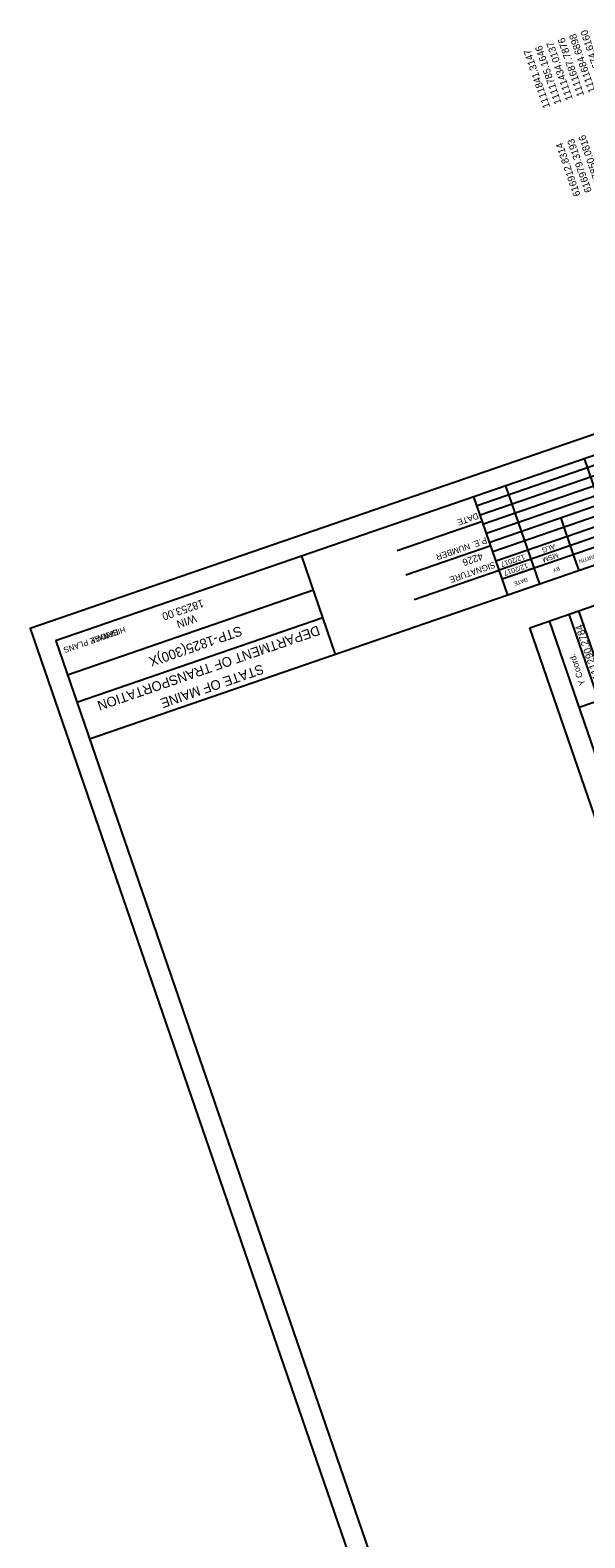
# Model space of a CAD drawing. Extents: x 1111039 to 1111836, y 617707 to 618808.
# Drawn here: x 1111039 to 1111305, y 618074 to 618798 of the extents above; entities that cross this region are included whole.
import ezdxf

# ---------------------------------------------------------------- set-up
doc = ezdxf.new("R2010")
doc.units = 0
for name, color, linetype in [('ANNOTATION', 7, 'Continuous'), ('BORDER', 7, 'Continuous'), ('BRIDGE_TITLE', 7, 'Continuous'), ('H_V CONTROLS', 7, 'Continuous'), ('HIGHWAY_TITLE', 7, 'Continuous'), ('PLOT BOUNDARY', 7, 'Continuous')]:
    doc.layers.add(name, color=color, linetype=linetype)

msp = doc.modelspace()

# ---------------------------------------------------------------- linework, layer by layer
at = {"layer": 'BORDER'}
for p, q in [((1111547.51, 618675.96), (1111051.11, 618505.04)), ((1111563.79, 618628.69), (1111067.39, 618457.77)), ((1111268.31, 618526.95), (1111252.03, 618574.22)), ((1111256.1, 618562.41), (1111215.22, 618548.33)), ((1111185.62, 618498.48), (1111169.34, 618545.75)), ((1111260.17, 618550.59), (1111219.29, 618536.51)), ((1111264.24, 618538.77), (1111223.36, 618524.69)), ((1111174.99, 618529.31), (1111056.8, 618488.62)), ((1111179.54, 618516.1), (1111061.35, 618475.4)), ((1111051.13, 618505.05), (1111311.58, 617748.63))]:
    msp.add_line(p, q, dxfattribs=at)
for points in [[(1111336.27, 618598.31), (1111253.55, 618569.82)], [(1111337.78, 618593.9), (1111255.07, 618565.42)], [(1111339.3, 618589.5), (1111256.58, 618561.02)], [(1111318.87, 618552.9), (1111305.22, 618592.54)], [(1111340.82, 618585.09), (1111258.1, 618556.61)], [(1111342.33, 618580.69), (1111259.62, 618552.21)], [(1111343.85, 618576.28), (1111261.13, 618547.8)], [(1111283.68, 618532.24), (1111267.4, 618579.52)], [(1111262.65, 618543.4), (1111345.37, 618571.88)], [(1111346.88, 618567.47), (1111264.17, 618538.99)], [(1111348.4, 618563.07), (1111269.02, 618535.74)], [(1111299.96, 618546.39), (1111293.89, 618564)], [(1111302.59, 618538.75), (1111299.96, 618546.39)], [(1111281.05, 618539.87), (1111265.68, 618534.58)]]:
    msp.add_lwpolyline(points, dxfattribs=at)
at = {"layer": 'H_V CONTROLS'}
for p, q in [((1111278.86, 618511.33), (1111354.5, 618537.37)), ((1111366.96, 618316.91), (1111297.77, 618517.84)), ((1111371.68, 618318.54), (1111302.5, 618519.46)), ((1111348.05, 618310.4), (1111278.86, 618511.33)), ((1111357.5, 618313.66), (1111288.32, 618514.58)), ((1111302.56, 618473.21), (1111368.75, 618496))]:
    msp.add_line(p, q, dxfattribs=at)
at = {"layer": 'PLOT BOUNDARY'}
msp.add_lwpolyline([(1111835.61, 617886.27), (1111558.88, 618689.96), (1111038.85, 618510.9), (1111315.58, 617707.21)], close=True, dxfattribs=at)

# ---------------------------------------------------------------- texts
at = {"layer": 'ANNOTATION'}
for s, height, rotation, p in [('1111674.6160', 3.45, 109, (1111315.95, 618770.78)), ('1111785.1646', 3.45, 109, (1111294.16, 618763.27)), ('1111434.0137', 3.45, 109, (1111299.61, 618765.15)), ('1111687.7876', 3.45, 109, (1111305.06, 618767.03)), ('1111684.6898', 3.45, 109, (1111310.5, 618768.9)), ('1111841.3147', 3.45, 109, (1111288.71, 618761.4)), ('617850.0816', 3.45, 109, (1111314.2, 618722.78)), ('616912.8314', 3.45, 109, (1111303.3, 618719.03)), ('616979.3193', 3.45, 109, (1111308.75, 618720.9)), ('4226', 3.396, 199, (1111255.73, 618547.36)), ('1111290.2784', 3.5156, 109, (1111313.74, 618484.77))]:
    msp.add_text(s, height=height, rotation=rotation, dxfattribs=at).set_placement(p)
at = {"layer": 'BORDER'}
for s, height, p in [('DATE', 2.953, (1111253.66, 618566.54)), ('P.E. NUMBER', 2.9528, (1111257.7, 618554.82)), ('12/2017', 2.423, (1111276.08, 618546.64)), ('ALG', 2.423, (1111290.66, 618551.66)), ('MSM', 2.423, (1111292.11, 618547.43)), ('ERNIE MARTIN', 1.8637, (1111319.67, 618549.94)), ('SIGNATURE', 2.953, (1111261.74, 618543.09)), ('12/2017', 2.423, (1111277.54, 618542.41)), ('BY', 1.857, (1111292.99, 618540.76)), ('DATE', 1.857, (1111277.52, 618535.43)), ('18253.00', 3.726, (1111121.52, 618525.03)), ('WIN', 3.726, (1111118, 618517.69)), ('DEPARTMENT OF TRANSPORTATION', 4.6588, (1111177.04, 618512.48)), ('STP-1825(300)X', 4.6588, (1111139.75, 618512.25)), ('STATE OF MAINE', 4.6588, (1111150.08, 618493.93))]:
    msp.add_text(s, height=height, rotation=199, dxfattribs=at).set_placement(p)
at = {"layer": 'BRIDGE_TITLE'}
msp.add_text('BRIDGE PLANS', height=2.795, rotation=199, dxfattribs=at).set_placement((1111080.75, 618510.79))
at = {"layer": 'H_V CONTROLS'}
msp.add_text('Y Coord.', height=3, rotation=109, dxfattribs=at).set_placement((1111305.64, 618484.23))
at = {"layer": 'HIGHWAY_TITLE'}
msp.add_text('HIGHWAY PLANS', height=2.795, rotation=199, dxfattribs=at).set_placement((1111084.1, 618511.95))

doc.saveas('drawing.dxf')
